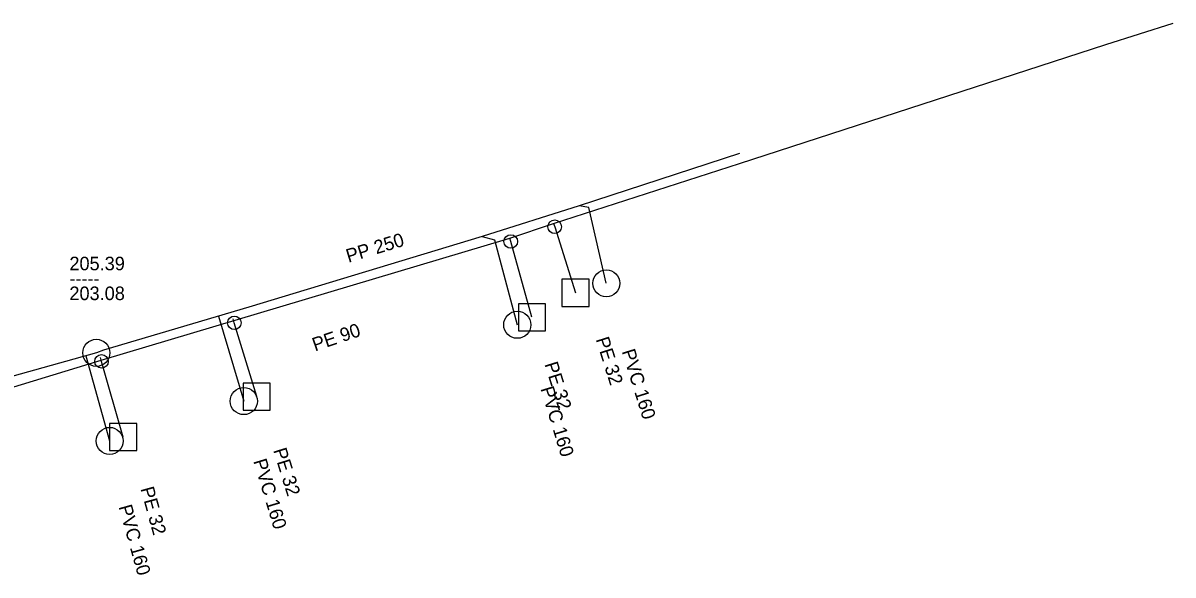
# Model space of a CAD drawing. Extents: x -686883 to -686397, y -1053920 to -1053689.
# Drawn here: x -686482.1 to -686397.3, y -1053766.7 to -1053726 of the extents above; entities that cross this region are included whole.
import ezdxf

# ---------------------------------------------------------------- set-up
doc = ezdxf.new("R2010")
doc.units = 0
doc.layers.add('Level 0', color=7, linetype='Continuous')

msp = doc.modelspace()

# ---------------------------------------------------------------- linework, layer by layer
at = {"layer": 'Level 0'}
for p, q in [((-686402.21, -1053727.58), (-686397.26, -1053726)), ((-686429.25, -1053736.36), (-686402.21, -1053727.58)), ((-686429.26, -1053735.62), (-686441.08, -1053739.48)), ((-686442.97, -1053740.79), (-686429.25, -1053736.36)), ((-686441.08, -1053739.48), (-686448.25, -1053741.74)), ((-686440.38, -1053739.62), (-686441.08, -1053739.48)), ((-686439.08, -1053745.2), (-686440.38, -1053739.62)), ((-686446.2, -1053741.88), (-686442.97, -1053740.79)), ((-686442.97, -1053740.79), (-686442.89, -1053741.03)), ((-686442.89, -1053741.03), (-686441.35, -1053745.9)), ((-686476.35, -1053750.87), (-686446.2, -1053741.88)), ((-686448.25, -1053741.74), (-686465.47, -1053746.97)), ((-686448.25, -1053741.74), (-686447.34, -1053741.99)), ((-686447.34, -1053741.99), (-686445.65, -1053748.26)), ((-686446.13, -1053742.12), (-686446.2, -1053741.88)), ((-686444.57, -1053747.71), (-686446.13, -1053742.12)), ((-686440.35, -1053744.9), (-686442.35, -1053744.9)), ((-686442.35, -1053744.9), (-686442.35, -1053746.9)), ((-686440.35, -1053746.9), (-686440.35, -1053744.9)), ((-686465.47, -1053746.97), (-686476.18, -1053750.14)), ((-686443.57, -1053746.71), (-686445.57, -1053746.71)), ((-686445.57, -1053746.71), (-686445.57, -1053748.71)), ((-686443.57, -1053748.71), (-686443.57, -1053746.71)), ((-686442.35, -1053746.9), (-686440.35, -1053746.9)), ((-686467.71, -1053747.63), (-686465.83, -1053753.89)), ((-686466.53, -1053748.12), (-686466.62, -1053747.83)), ((-686464.88, -1053753.56), (-686466.53, -1053748.12)), ((-686445.57, -1053748.71), (-686443.57, -1053748.71)), ((-686476.71, -1053750.33), (-686491.84, -1053754.55)), ((-686477.48, -1053750.54), (-686475.73, -1053756.83)), ((-686476.18, -1053750.14), (-686476.71, -1053750.33)), ((-686493.21, -1053755.99), (-686476.35, -1053750.87)), ((-686476.33, -1053750.96), (-686476.41, -1053750.67)), ((-686474.73, -1053756.54), (-686476.33, -1053750.96)), ((-686463.88, -1053752.56), (-686465.88, -1053752.56)), ((-686465.88, -1053752.56), (-686465.88, -1053754.56)), ((-686463.88, -1053754.56), (-686463.88, -1053752.56)), ((-686465.88, -1053754.56), (-686463.88, -1053754.56)), ((-686473.73, -1053755.54), (-686475.73, -1053755.54)), ((-686475.73, -1053755.54), (-686475.73, -1053757.54)), ((-686473.73, -1053757.54), (-686473.73, -1053755.54)), ((-686475.73, -1053757.54), (-686473.73, -1053757.54))]:
    msp.add_line(p, q, dxfattribs=at)
for centre, radius in [((-686442.89, -1053741.03), 0.5), ((-686446.13, -1053742.12), 0.5), ((-686439.08, -1053745.2), 1), ((-686466.53, -1053748.12), 0.5), ((-686445.65, -1053748.26), 1), ((-686476.71, -1053750.33), 1), ((-686476.33, -1053750.96), 0.5), ((-686465.83, -1053753.89), 1), ((-686475.73, -1053756.83), 1)]:
    msp.add_circle(centre, radius, dxfattribs=at)

# ---------------------------------------------------------------- texts
for s, rotation, p in [('PP 250', 16.894, (-686458.11, -1053743.69)), ('PE 90', 18.648, (-686460.58, -1053750.23)), ('PE 32', 287.548, (-686439.87, -1053749.33)), ('PVC 160', 287.311, (-686437.95, -1053750.22)), ('PE 32', 287.241, (-686443.65, -1053751.16)), ('PVC 160', 286.892, (-686443.95, -1053752.97)), ('PE 32', 287.241, (-686463.67, -1053757.51)), ('PVC 160', 286.845, (-686465.14, -1053758.31)), ('PE 32', 285.422, (-686473.46, -1053760.35)), ('PVC 160', 285.584, (-686475.08, -1053761.68))]:
    msp.add_text(s, height=1, rotation=rotation, dxfattribs=at).set_placement(p)
for s, p in [('205.39', (-686478.7, -1053744.24)), ('-----', (-686478.7, -1053745.34)), ('203.08', (-686478.7, -1053746.44))]:
    msp.add_text(s, height=1, dxfattribs=at).set_placement(p)

doc.saveas('drawing.dxf')
